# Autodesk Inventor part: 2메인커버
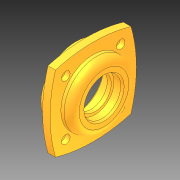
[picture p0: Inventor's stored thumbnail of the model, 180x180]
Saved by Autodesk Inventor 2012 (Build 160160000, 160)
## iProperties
Created: 2012-07
Part Number: 2메인커버
Material: Default
Document SubType Name: Modeling
Designer: JANG KYOUNG-IL
Density: 1 g/cm^3
Author: JANG KYOUNG-IL
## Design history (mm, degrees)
node "작업축1"
node "작업 평면2"
node "작업점1"
sketch "스케치12"
  geometry: L1 (-46.5, 57.5)-(-72.5, 57.5); L2 (-46.5, 90)-(-55.5, 90); L3 (-55.5, 90)-(-55.5, 87.5); L4 (-55.5, 87.5)-(-72.5, 87.5); L5 (-72.5, 87.5)-(-72.5, 75); L6 (-72.5, 75)-(-64.2, 75); L7 (-64.2, 75)-(-64.2, 72.5); L8 (-64.2, 72.5)-(-60.5, 72.5); L9 (-60.5, 72.5)-(-60.5, 81); L10 (-60.5, 81)-(-46.5, 81); L11 (-46.5, 81)-(-46.5, 90); 1 further point
  constraints: 22 end point, 8 parallel, 4 point on line, 2 vertical, 1 horizontal
  dimensions: "d87" = 8.3 horizontal distance of L7.end L5.end; "d88" = 14 horizontal distance of L8.end L10.end; "d89" = 30 diameter of L8 L1; "d90" = 35 diameter of L6 L1; "d91" = 47 diameter of L10 L1; "d92" = 65 diameter of L2 L1; "d93" = 60 diameter of L4 L1; "d95" = 9 distance of L2.start L2.end; "d96" = 26 horizontal distance of L4.end L2.start
revolve "회전1" sketch "스케치12" stored, may be unused: angle "d97" = 90 deg
sketch "스케치13"
  geometry: L1 (-35.002, 92.502)-(35.002, 92.502); L2 (35.002, 92.502)-(35.002, 22.498); L3 (35.002, 22.498)-(-35.002, 22.498); L4 (-35.002, 22.498)-(-35.002, 92.502); C1 r 23.5 at (0, 57.5) reference; A1 r 125.055 centre (0, -27.555) between (35.002, 92.502) and (-35.002, 92.502); A2 r 125.055 centre (0, 142.555) between (-35.002, 22.498) and (35.002, 22.498); A3 r 125.055 centre (85.055, 57.5) between (-35.002, 92.502) and (-35.002, 22.498); A4 r 125.055 centre (-85.055, 57.5) between (35.002, 22.498) and (35.002, 92.502); 4 further points
  constraints: 8 end point, 8 point on circle, 4 centre point, 2 equal radius, 2 midpoint, 2 parallel, 2 perpendicular, 1 horizontal, 1 horizontal alignment, 1 vertical alignment
  dimensions: "d98" = 99 distance of L1.end L3.end; "d99" = 80 dimension on A2 A1; "d100" = 80 dimension on A4 A3
extrude "돌출10" join sketch "스케치13" distance "d101" = 7; taper "d102" = 0 deg
fillet "모깎기7" dims "d103" = 7
chamfer "모따기2" distance "d104" = 2; stored, may be unused: second distance "d105" = 2, angle "d106" = 30 deg
fillet "모깎기8" dims "d107" = 0.3
chamfer "모따기3" distance "d108" = 2; stored, may be unused: second distance "d109" = 2, angle "d110" = 30 deg
sketch "스케치14"
  geometry: L1 (-57.5, 0)-(-93.53, 0); A1 r 36.03 centre (-57.5, 0) between (-82.977, 25.477) and (-93.53, 0); 2 further points
  constraints: 2 end point, 2 point on circle, 1 centre point, 1 coincident, 1 horizontal
  dimensions: "d111" = 45 deg dimension on point (-57.5, 0) L1.end A1.start
hole "구멍3" sketch "스케치14" at (-57.5, 0), (-82.977, 25.477) diameter "d112" = 4.5; stored, may be unused: countersink angle "d116" = 90 deg, drill point angle "d118" = 118 deg; dims "d113" = 6, "d114" = 8, "d115" = 4.4, "d117" = 8
node "작업 평면3"
node "솔리드1"
mirror "대칭3"
mirror "대칭4"
node "솔리드3"
other parameters: "d83" = 55.5, "d119" = 90 deg
